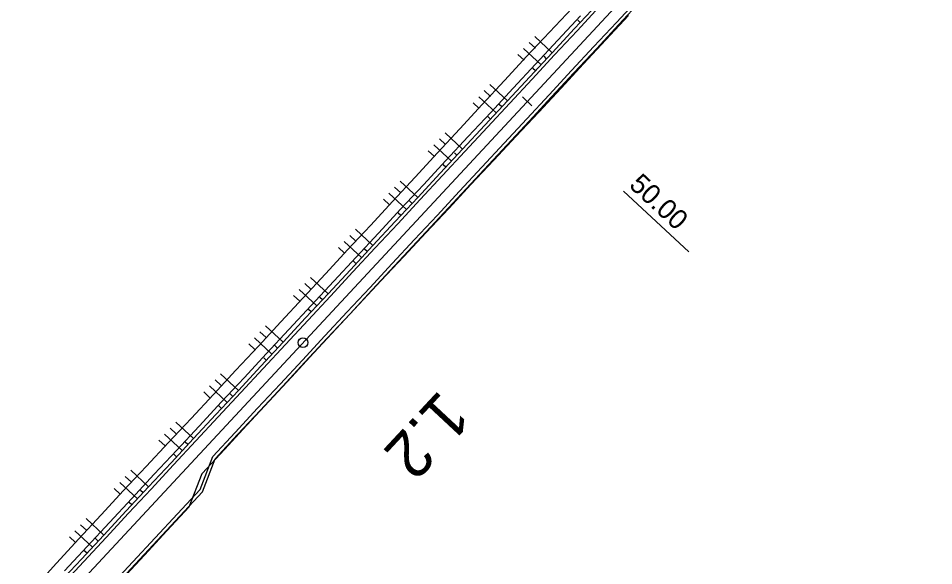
# Model space of a CAD drawing. Extents: x -481656 to -478728, y -1113199 to -1110710.
# Drawn here: x -479136.3 to -478997.3, y -1110940.2 to -1110857.1 of the extents above; entities that cross this region are included whole.
import ezdxf

# ---------------------------------------------------------------- set-up
doc = ezdxf.new("R2010")
doc.units = 0
for name, color, linetype in [('C5_HATCH_SLOPE_L', 7, 'Continuous'), ('C5_HATCH_SLOPE_R', 7, 'Continuous'), ('C5_HECTOMETRY', 7, 'Continuous'), ('C5_HRANA_TELESO', 7, 'Continuous'), ('C5_KORUNA', 7, 'Continuous'), ('C5_OSA', 7, 'Continuous'), ('C5_PRIKOP', 7, 'Continuous'), ('C5_STANICENI', 7, 'Continuous'), ('C5_ZPEVKRAJ', 7, 'Continuous')]:
    doc.layers.add(name, color=color, linetype=linetype)

msp = doc.modelspace()

# ---------------------------------------------------------------- linework, layer by layer
at = {"layer": 'C5_HATCH_SLOPE_L'}
for p, q in [((-479050.93, -1110857.74), (-479051.31, -1110857.38)), ((-479055.18, -1110862.32), (-479057.82, -1110859.86)), ((-479056.88, -1110864.15), (-479059.53, -1110861.69)), ((-479057.75, -1110861.64), (-479058.68, -1110860.77)), ((-479059.45, -1110863.47), (-479060.39, -1110862.6)), ((-479056.03, -1110863.23), (-479056.42, -1110862.87)), ((-479057.74, -1110865.06), (-479058.13, -1110864.7)), ((-479061.99, -1110869.64), (-479064.65, -1110867.17)), ((-479063.69, -1110871.47), (-479066.35, -1110869)), ((-479064.57, -1110868.95), (-479065.5, -1110868.08)), ((-479066.27, -1110870.78), (-479067.21, -1110869.91)), ((-479062.84, -1110870.56), (-479063.24, -1110870.19)), ((-479064.55, -1110872.39), (-479064.94, -1110872.02)), ((-479068.8, -1110876.96), (-479071.46, -1110874.49)), ((-479071.38, -1110876.27), (-479072.31, -1110875.4)), ((-479073.08, -1110878.1), (-479074.02, -1110877.24)), ((-479070.5, -1110878.79), (-479073.17, -1110876.32)), ((-479069.65, -1110877.88), (-479070.05, -1110877.51)), ((-479071.35, -1110879.71), (-479071.75, -1110879.34)), ((-479078.19, -1110883.59), (-479079.12, -1110882.73)), ((-479075.61, -1110884.29), (-479078.27, -1110881.81)), ((-479077.31, -1110886.12), (-479079.98, -1110883.64)), ((-479079.89, -1110885.42), (-479080.83, -1110884.56)), ((-479076.46, -1110885.2), (-479076.86, -1110884.83)), ((-479078.17, -1110887.03), (-479078.56, -1110886.66)), ((-479082.42, -1110891.61), (-479085.08, -1110889.13)), ((-479084.12, -1110893.44), (-479086.79, -1110890.96)), ((-479085, -1110890.91), (-479085.94, -1110890.05)), ((-479086.71, -1110892.74), (-479087.64, -1110891.88)), ((-479083.27, -1110892.52), (-479083.67, -1110892.15)), ((-479084.98, -1110894.35), (-479085.38, -1110893.98)), ((-479089.23, -1110898.93), (-479091.9, -1110896.45)), ((-479091.82, -1110898.23), (-479092.75, -1110897.37)), ((-479093.52, -1110900.06), (-479094.46, -1110899.2)), ((-479090.93, -1110900.76), (-479093.6, -1110898.28)), ((-479090.08, -1110899.85), (-479090.48, -1110899.47)), ((-479091.79, -1110901.68), (-479092.19, -1110901.3)), ((-479096.04, -1110906.26), (-479098.72, -1110903.77)), ((-479098.64, -1110905.55), (-479099.57, -1110904.68)), ((-479100.34, -1110907.38), (-479101.28, -1110906.51)), ((-479097.74, -1110908.09), (-479100.42, -1110905.59)), ((-479096.89, -1110907.17), (-479097.3, -1110906.79)), ((-479098.6, -1110909), (-479099, -1110908.62)), ((-479105.46, -1110912.86), (-479106.39, -1110911.99)), ((-479102.85, -1110913.58), (-479105.54, -1110911.08)), ((-479104.55, -1110915.41), (-479107.24, -1110912.91)), ((-479107.16, -1110914.69), (-479108.1, -1110913.82)), ((-479103.7, -1110914.49), (-479104.11, -1110914.11)), ((-479105.41, -1110916.32), (-479105.81, -1110915.94)), ((-479109.66, -1110920.9), (-479112.36, -1110918.39)), ((-479111.36, -1110922.73), (-479114.06, -1110920.22)), ((-479112.27, -1110920.18), (-479113.21, -1110919.31)), ((-479113.97, -1110922.01), (-479114.91, -1110921.14)), ((-479110.51, -1110921.82), (-479110.92, -1110921.44)), ((-479112.22, -1110923.65), (-479112.62, -1110923.27)), ((-479116.47, -1110928.22), (-479119.17, -1110925.71)), ((-479119.08, -1110927.51), (-479120.02, -1110926.63)), ((-479120.78, -1110929.34), (-479121.72, -1110928.46)), ((-479118.17, -1110930.05), (-479120.87, -1110927.54)), ((-479117.32, -1110929.14), (-479117.73, -1110928.76)), ((-479119.02, -1110930.97), (-479119.43, -1110930.59)), ((-479125.88, -1110934.84), (-479126.82, -1110933.97)), ((-479123.28, -1110935.55), (-479125.97, -1110933.04)), ((-479124.98, -1110937.38), (-479127.66, -1110934.89)), ((-479127.58, -1110936.67), (-479128.51, -1110935.81)), ((-479124.13, -1110936.46), (-479124.54, -1110936.09)), ((-479125.83, -1110938.29), (-479126.24, -1110937.92))]:
    msp.add_line(p, q, dxfattribs=at)
at = {"layer": 'C5_HATCH_SLOPE_R'}
for p, q in [((-479047.12, -1110860.26), (-479047.03, -1110860.35)), ((-479047.98, -1110861.18), (-479047.93, -1110861.22)), ((-479047.88, -1110861.27), (-479047.88, -1110861.27)), ((-479049.68, -1110863.01), (-479049.63, -1110863.06)), ((-479049.58, -1110863.1), (-479049.58, -1110863.1)), ((-479048.83, -1110862.09), (-479048.73, -1110862.19)), ((-479053.93, -1110867.58), (-479053.83, -1110867.69)), ((-479054.79, -1110868.5), (-479054.73, -1110868.55)), ((-479054.68, -1110868.6), (-479054.68, -1110868.6)), ((-479056.49, -1110870.33), (-479056.44, -1110870.38)), ((-479055.64, -1110869.42), (-479055.53, -1110869.51)), ((-479056.39, -1110870.43), (-479056.39, -1110870.43)), ((-479061.6, -1110875.82), (-479061.55, -1110875.86)), ((-479061.51, -1110875.9), (-479061.51, -1110875.9)), ((-479060.74, -1110874.91), (-479060.66, -1110874.99)), ((-479062.45, -1110876.74), (-479062.36, -1110876.82)), ((-479063.3, -1110877.65), (-479063.26, -1110877.69)), ((-479063.22, -1110877.73), (-479063.22, -1110877.73)), ((-479067.55, -1110882.23), (-479067.49, -1110882.29)), ((-479069.26, -1110884.06), (-479069.19, -1110884.12)), ((-479068.41, -1110883.15), (-479068.37, -1110883.18)), ((-479068.34, -1110883.21), (-479068.34, -1110883.21)), ((-479070.11, -1110884.98), (-479070.08, -1110885)), ((-479070.05, -1110885.03), (-479070.05, -1110885.03)), ((-479074.36, -1110889.55), (-479074.32, -1110889.6)), ((-479075.22, -1110890.47), (-479075.19, -1110890.49)), ((-479075.17, -1110890.51), (-479075.17, -1110890.51)), ((-479076.92, -1110892.3), (-479076.9, -1110892.32)), ((-479076.88, -1110892.34), (-479076.88, -1110892.34)), ((-479076.07, -1110891.38), (-479076.02, -1110891.43)), ((-479082.03, -1110897.79), (-479082.01, -1110897.8)), ((-479082, -1110897.82), (-479082, -1110897.82)), ((-479081.17, -1110896.88), (-479081.15, -1110896.9)), ((-479082.88, -1110898.71), (-479082.85, -1110898.73)), ((-479083.73, -1110899.62), (-479083.72, -1110899.63)), ((-479083.71, -1110899.64), (-479083.71, -1110899.64)), ((-479088.84, -1110905.11), (-479088.83, -1110905.12)), ((-479088.82, -1110905.13), (-479088.82, -1110905.13)), ((-479087.98, -1110904.2), (-479087.97, -1110904.22)), ((-479089.69, -1110906.03), (-479089.67, -1110906.05)), ((-479090.54, -1110906.95), (-479090.53, -1110906.96)), ((-479090.52, -1110906.97), (-479090.52, -1110906.97)), ((-479094.79, -1110911.52), (-479094.77, -1110911.55)), ((-479096.5, -1110913.35), (-479096.47, -1110913.38)), ((-479095.65, -1110912.44), (-479095.63, -1110912.45)), ((-479095.62, -1110912.47), (-479095.62, -1110912.47)), ((-479097.35, -1110914.27), (-479097.33, -1110914.28)), ((-479097.32, -1110914.3), (-479097.32, -1110914.3)), ((-479101.6, -1110918.84), (-479101.56, -1110918.88)), ((-479102.46, -1110919.76), (-479102.43, -1110919.78)), ((-479102.41, -1110919.8), (-479102.41, -1110919.8)), ((-479104.16, -1110921.59), (-479104.14, -1110921.61)), ((-479104.11, -1110921.63), (-479104.11, -1110921.63)), ((-479103.31, -1110920.68), (-479103.26, -1110920.72)), ((-479108.41, -1110926.17), (-479108.36, -1110926.21)), ((-479109.38, -1110928.68), (-479109.33, -1110928.73)), ((-479108.9, -1110927.42), (-479108.87, -1110927.45)), ((-479108.85, -1110927.47), (-479108.85, -1110927.47)), ((-479109.87, -1110929.94), (-479109.84, -1110929.96)), ((-479109.82, -1110929.98), (-479109.82, -1110929.98)), ((-479113.76, -1110934.85), (-479113.71, -1110934.9)), ((-479115.46, -1110936.68), (-479115.41, -1110936.74)), ((-479114.61, -1110935.77), (-479114.58, -1110935.79)), ((-479114.56, -1110935.82), (-479114.56, -1110935.82)), ((-479116.31, -1110937.6), (-479116.28, -1110937.63)), ((-479116.26, -1110937.65), (-479116.26, -1110937.65))]:
    msp.add_line(p, q, dxfattribs=at)
at = {"layer": 'C5_HECTOMETRY'}
msp.add_circle((-479093.04, -1110906.33), 0.75, dxfattribs=at)
at = {"layer": 'C5_HRANA_TELESO'}
for p, q in [((-479055.59, -1110859.22), (-479052.16, -1110855.58)), ((-479047.03, -1110860.35), (-479043.62, -1110856.69)), ((-479059.02, -1110862.86), (-479055.59, -1110859.22)), ((-479050.43, -1110864.02), (-479047.03, -1110860.35)), ((-479062.42, -1110866.52), (-479059.02, -1110862.86)), ((-479053.83, -1110867.69), (-479050.43, -1110864.02)), ((-479065.82, -1110870.19), (-479062.42, -1110866.52)), ((-479057.24, -1110871.34), (-479053.83, -1110867.69)), ((-479069.21, -1110873.86), (-479065.82, -1110870.19)), ((-479060.66, -1110874.99), (-479057.24, -1110871.34)), ((-479072.61, -1110877.53), (-479069.21, -1110873.86)), ((-479064.07, -1110878.64), (-479060.66, -1110874.99)), ((-479076.01, -1110881.2), (-479072.61, -1110877.53)), ((-479067.49, -1110882.29), (-479064.07, -1110878.64)), ((-479079.41, -1110884.86), (-479076.01, -1110881.2)), ((-479070.9, -1110885.95), (-479067.49, -1110882.29)), ((-479082.8, -1110888.53), (-479079.41, -1110884.86)), ((-479074.32, -1110889.6), (-479070.9, -1110885.95)), ((-479086.2, -1110892.2), (-479082.8, -1110888.53)), ((-479077.73, -1110893.25), (-479074.32, -1110889.6)), ((-479089.6, -1110895.87), (-479086.2, -1110892.2)), ((-479081.15, -1110896.9), (-479077.73, -1110893.25)), ((-479093, -1110899.53), (-479089.6, -1110895.87)), ((-479084.56, -1110900.55), (-479081.15, -1110896.9)), ((-479096.41, -1110903.2), (-479093, -1110899.53)), ((-479087.97, -1110904.22), (-479084.56, -1110900.55)), ((-479099.81, -1110906.86), (-479096.41, -1110903.2)), ((-479091.37, -1110907.88), (-479087.97, -1110904.22)), ((-479103.21, -1110910.52), (-479099.81, -1110906.86)), ((-479094.77, -1110911.55), (-479091.37, -1110907.88)), ((-479106.61, -1110914.19), (-479103.21, -1110910.52)), ((-479098.17, -1110915.22), (-479094.77, -1110911.55)), ((-479110.02, -1110917.85), (-479106.61, -1110914.19)), ((-479101.56, -1110918.88), (-479098.17, -1110915.22)), ((-479113.43, -1110921.5), (-479110.02, -1110917.85)), ((-479104.96, -1110922.55), (-479101.56, -1110918.88)), ((-479116.86, -1110925.14), (-479113.43, -1110921.5)), ((-479108.36, -1110926.21), (-479104.96, -1110922.55)), ((-479120.27, -1110928.79), (-479116.86, -1110925.14)), ((-479110.3, -1110931.24), (-479108.36, -1110926.21)), ((-479123.68, -1110932.45), (-479120.27, -1110928.79)), ((-479113.71, -1110934.9), (-479110.3, -1110931.24)), ((-479127.07, -1110936.13), (-479123.68, -1110932.45)), ((-479117.11, -1110938.57), (-479113.71, -1110934.9)), ((-479130.46, -1110939.81), (-479127.07, -1110936.13)), ((-479133.82, -1110943.51), (-479130.46, -1110939.81)), ((-479120.5, -1110942.24), (-479117.11, -1110938.57))]:
    msp.add_line(p, q, dxfattribs=at)
at = {"layer": 'C5_KORUNA'}
for p, q in [((-479051.78, -1110858.66), (-479048.37, -1110854.99)), ((-479045.08, -1110858.06), (-479041.67, -1110854.4)), ((-479055.18, -1110862.32), (-479051.78, -1110858.66)), ((-479048.48, -1110861.72), (-479045.08, -1110858.06)), ((-479051.89, -1110865.38), (-479048.48, -1110861.72)), ((-479058.59, -1110865.98), (-479055.18, -1110862.32)), ((-479061.99, -1110869.64), (-479058.59, -1110865.98)), ((-479055.29, -1110869.04), (-479051.89, -1110865.38)), ((-479065.4, -1110873.3), (-479061.99, -1110869.64)), ((-479058.7, -1110872.71), (-479055.29, -1110869.04)), ((-479062.1, -1110876.37), (-479058.7, -1110872.71)), ((-479068.8, -1110876.96), (-479065.4, -1110873.3)), ((-479072.21, -1110880.62), (-479068.8, -1110876.96)), ((-479065.51, -1110880.03), (-479062.1, -1110876.37)), ((-479068.91, -1110883.69), (-479065.51, -1110880.03)), ((-479075.61, -1110884.29), (-479072.21, -1110880.62)), ((-479079.02, -1110887.95), (-479075.61, -1110884.29)), ((-479072.32, -1110887.35), (-479068.91, -1110883.69)), ((-479082.42, -1110891.61), (-479079.02, -1110887.95)), ((-479075.72, -1110891.01), (-479072.32, -1110887.35)), ((-479079.13, -1110894.67), (-479075.72, -1110891.01)), ((-479085.83, -1110895.27), (-479082.42, -1110891.61)), ((-479089.23, -1110898.93), (-479085.83, -1110895.27)), ((-479082.53, -1110898.33), (-479079.13, -1110894.67)), ((-479092.64, -1110902.59), (-479089.23, -1110898.93)), ((-479085.94, -1110902), (-479082.53, -1110898.33)), ((-479089.34, -1110905.66), (-479085.94, -1110902)), ((-479096.04, -1110906.26), (-479092.64, -1110902.59)), ((-479099.45, -1110909.92), (-479096.04, -1110906.26)), ((-479092.75, -1110909.32), (-479089.34, -1110905.66)), ((-479096.15, -1110912.98), (-479092.75, -1110909.32)), ((-479102.85, -1110913.58), (-479099.45, -1110909.92)), ((-479099.56, -1110916.64), (-479096.15, -1110912.98)), ((-479106.26, -1110917.24), (-479102.85, -1110913.58)), ((-479109.66, -1110920.9), (-479106.26, -1110917.24)), ((-479102.96, -1110920.3), (-479099.56, -1110916.64)), ((-479106.37, -1110923.97), (-479102.96, -1110920.3)), ((-479113.07, -1110924.56), (-479109.66, -1110920.9)), ((-479116.47, -1110928.22), (-479113.07, -1110924.56)), ((-479108.31, -1110928.99), (-479106.37, -1110923.97)), ((-479119.88, -1110931.89), (-479116.47, -1110928.22)), ((-479111.71, -1110932.65), (-479108.31, -1110928.99)), ((-479123.28, -1110935.55), (-479119.88, -1110931.89)), ((-479115.12, -1110936.31), (-479111.71, -1110932.65)), ((-479126.69, -1110939.21), (-479123.28, -1110935.55)), ((-479118.52, -1110939.97), (-479115.12, -1110936.31)), ((-479130.09, -1110942.87), (-479126.69, -1110939.21)), ((-479121.93, -1110943.64), (-479118.52, -1110939.97))]:
    msp.add_line(p, q, dxfattribs=at)
at = {"layer": 'C5_OSA'}
msp.add_line((-479231.87, -1111055.62), (-478997.26, -1110803.33), dxfattribs=at)
at = {"layer": 'C5_PRIKOP'}
for p, q in [((-479054.31, -1110860.41), (-479050.91, -1110856.74)), ((-479057.72, -1110864.07), (-479054.31, -1110860.41)), ((-479061.12, -1110867.73), (-479057.72, -1110864.07)), ((-479064.53, -1110871.39), (-479061.12, -1110867.73)), ((-479067.93, -1110875.05), (-479064.53, -1110871.39)), ((-479071.34, -1110878.71), (-479067.93, -1110875.05)), ((-479074.74, -1110882.37), (-479071.34, -1110878.71)), ((-479078.15, -1110886.03), (-479074.74, -1110882.37)), ((-479081.55, -1110889.7), (-479078.15, -1110886.03)), ((-479084.96, -1110893.36), (-479081.55, -1110889.7)), ((-479088.36, -1110897.02), (-479084.96, -1110893.36)), ((-479091.77, -1110900.68), (-479088.36, -1110897.02)), ((-479095.17, -1110904.34), (-479091.77, -1110900.68)), ((-479098.58, -1110908), (-479095.17, -1110904.34)), ((-479101.98, -1110911.67), (-479098.58, -1110908)), ((-479105.39, -1110915.33), (-479101.98, -1110911.67)), ((-479108.79, -1110918.99), (-479105.39, -1110915.33)), ((-479112.2, -1110922.65), (-479108.79, -1110918.99)), ((-479115.61, -1110926.3), (-479112.2, -1110922.65)), ((-479119.02, -1110929.97), (-479115.61, -1110926.3)), ((-479122.42, -1110933.63), (-479119.02, -1110929.97)), ((-479125.83, -1110937.29), (-479122.42, -1110933.63)), ((-479129.23, -1110940.95), (-479125.83, -1110937.29))]:
    msp.add_line(p, q, dxfattribs=at)
at = {"layer": 'C5_STANICENI'}
for p, q in [((-479058.26, -1110870.4), (-479059.72, -1110869.03)), ((-479044.34, -1110883.33), (-479034.46, -1110892.53))]:
    msp.add_line(p, q, dxfattribs=at)
at = {"layer": 'C5_ZPEVKRAJ'}
for p, q in [((-479045.44, -1110857.72), (-479042.04, -1110854.06)), ((-479051.41, -1110859), (-479048.01, -1110855.33)), ((-479048.85, -1110861.38), (-479045.44, -1110857.72)), ((-479054.82, -1110862.66), (-479051.41, -1110859)), ((-479052.25, -1110865.04), (-479048.85, -1110861.38)), ((-479058.22, -1110866.32), (-479054.82, -1110862.66)), ((-479055.66, -1110868.7), (-479052.25, -1110865.04)), ((-479061.63, -1110869.98), (-479058.22, -1110866.32)), ((-479059.06, -1110872.36), (-479055.66, -1110868.7)), ((-479065.03, -1110873.64), (-479061.63, -1110869.98)), ((-479062.47, -1110876.03), (-479059.06, -1110872.36)), ((-479068.44, -1110877.3), (-479065.03, -1110873.64)), ((-479071.84, -1110880.97), (-479068.44, -1110877.3)), ((-479065.87, -1110879.69), (-479062.47, -1110876.03)), ((-479069.28, -1110883.35), (-479065.87, -1110879.69)), ((-479075.24, -1110884.63), (-479071.84, -1110880.97)), ((-479072.68, -1110887.01), (-479069.28, -1110883.35)), ((-479078.65, -1110888.29), (-479075.24, -1110884.63)), ((-479076.09, -1110890.67), (-479072.68, -1110887.01)), ((-479082.05, -1110891.95), (-479078.65, -1110888.29)), ((-479079.49, -1110894.33), (-479076.09, -1110890.67)), ((-479085.46, -1110895.61), (-479082.05, -1110891.95)), ((-479082.9, -1110898), (-479079.49, -1110894.33)), ((-479088.86, -1110899.27), (-479085.46, -1110895.61)), ((-479086.3, -1110901.66), (-479082.9, -1110898)), ((-479092.27, -1110902.93), (-479088.86, -1110899.27)), ((-479089.71, -1110905.32), (-479086.3, -1110901.66)), ((-479095.67, -1110906.6), (-479092.27, -1110902.93)), ((-479093.11, -1110908.98), (-479089.71, -1110905.32)), ((-479099.08, -1110910.26), (-479095.67, -1110906.6)), ((-479096.52, -1110912.64), (-479093.11, -1110908.98)), ((-479102.48, -1110913.92), (-479099.08, -1110910.26)), ((-479099.92, -1110916.3), (-479096.52, -1110912.64)), ((-479105.89, -1110917.58), (-479102.48, -1110913.92)), ((-479109.29, -1110921.24), (-479105.89, -1110917.58)), ((-479103.33, -1110919.96), (-479099.92, -1110916.3)), ((-479106.73, -1110923.62), (-479103.33, -1110919.96)), ((-479112.7, -1110924.9), (-479109.29, -1110921.24)), ((-479108.67, -1110928.65), (-479106.73, -1110923.62)), ((-479116.1, -1110928.56), (-479112.7, -1110924.9)), ((-479119.51, -1110932.23), (-479116.1, -1110928.56)), ((-479112.08, -1110932.31), (-479108.67, -1110928.65)), ((-479122.91, -1110935.89), (-479119.51, -1110932.23)), ((-479115.48, -1110935.97), (-479112.08, -1110932.31)), ((-479126.32, -1110939.55), (-479122.91, -1110935.89)), ((-479118.89, -1110939.63), (-479115.48, -1110935.97)), ((-479129.72, -1110943.21), (-479126.32, -1110939.55)), ((-479122.29, -1110943.29), (-479118.89, -1110939.63))]:
    msp.add_line(p, q, dxfattribs=at)

# ---------------------------------------------------------------- texts
at = {"layer": 'C5_HECTOMETRY'}
msp.add_text('1.2', height=7, rotation=227.0337, dxfattribs=at).set_placement((-479072.23, -1110913.33))
at = {"layer": 'C5_STANICENI'}
msp.add_text('50.00', height=2.999, rotation=317.0793, dxfattribs=at).set_placement((-479043.66, -1110882.6))

doc.saveas('drawing.dxf')
